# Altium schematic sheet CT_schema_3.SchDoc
size 287 x 169 mm
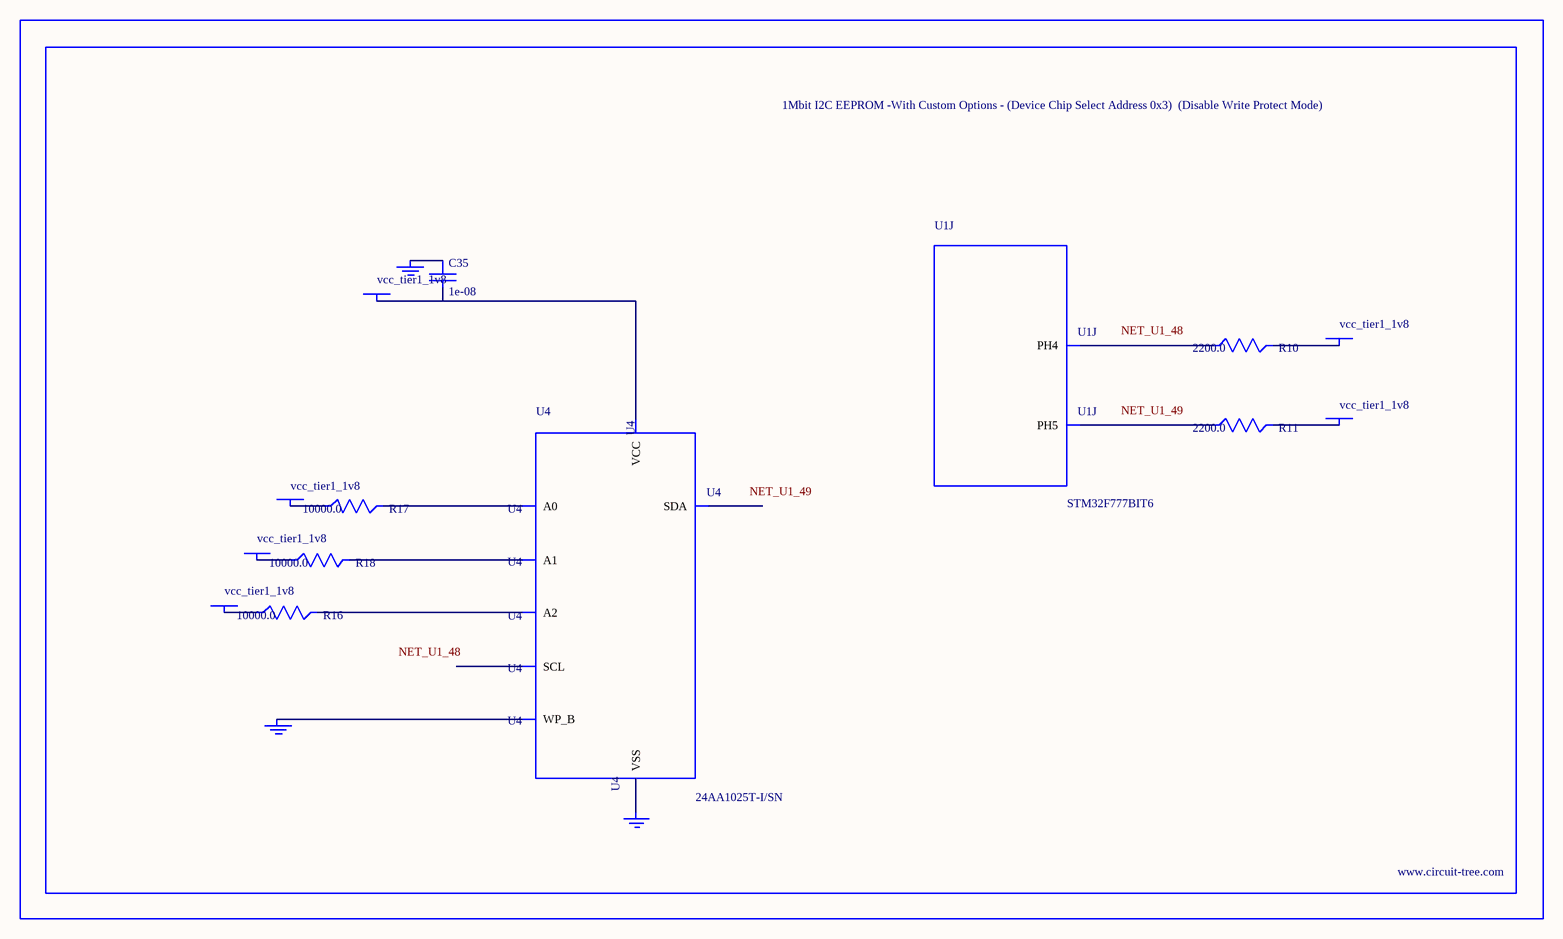
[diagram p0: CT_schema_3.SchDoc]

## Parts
BORDER2  (no value)
C35  1e-08  [C0402]
GND_INSTANCE_2_0  (no value)
GND_INSTANCE_2_1  (no value)
GND_INSTANCE_2_2  (no value)
POWER_INSTANCE_2_0  vcc_tier1_1v8
POWER_INSTANCE_2_1  vcc_tier1_1v8
POWER_INSTANCE_2_2  vcc_tier1_1v8
POWER_INSTANCE_2_3  vcc_tier1_1v8
POWER_INSTANCE_2_4  vcc_tier1_1v8
POWER_INSTANCE_2_5  vcc_tier1_1v8
R10  2200.0  [R0603]
R11  2200.0  [R0603]
R16  10000.0  [R0603]
R17  10000.0  [R0603]
R18  10000.0  [R0603]
U1  STM32F777BIT6  [LQFP208]  (part J of 15)
U4  24AA1025T-I/SN  [SOIC-8]

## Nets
NetC35_1: C35.1 GND_INSTANCE_2_1.0(GND)
NetC35_2: C35.2 POWER_INSTANCE_2_3.0(PWR) U4.8(VCC)
NetGND_INSTANCE_2_0_0: GND_INSTANCE_2_0.0(GND) U4.7(WP_B)
NetGND_INSTANCE_2_2_0: GND_INSTANCE_2_2.0(GND) U4.4(VSS)
NetPOWER_INSTANCE_2_0_0: POWER_INSTANCE_2_0.0(PWR) R17.1
NetPOWER_INSTANCE_2_1_0: POWER_INSTANCE_2_1.0(PWR) R18.1
NetPOWER_INSTANCE_2_2_0: POWER_INSTANCE_2_2.0(PWR) R16.1
NetPOWER_INSTANCE_2_4_0: POWER_INSTANCE_2_4.0(PWR) R10.2
NetPOWER_INSTANCE_2_5_0: POWER_INSTANCE_2_5.0(PWR) R11.2
NetR10_1: R10.1 U1.48(PH4)
NetR11_1: R11.1 U1.49(PH5)
NetR16_2: R16.2 U4.3(A2)
NetR17_2: R17.2 U4.1(A0)
NetR18_2: R18.2 U4.2(A1)

Not connected (* = marked no-connect by the designer): U4 5(SDA) 6(SCL)

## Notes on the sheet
- Labels drawn without touching a wire or pin: NET_U1_48, NET_U1_49

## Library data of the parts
BORDER2 = BORDER_PAGE2
C35 = C0402C103K3RAC
GND_INSTANCE_2_0-GND_INSTANCE_2_2 = GND
POWER_INSTANCE_2_0-POWER_INSTANCE_2_5 = PWR
R10 R11 = RC0603JR-072K2L
R16-R18 = RC0603JR-0710KL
